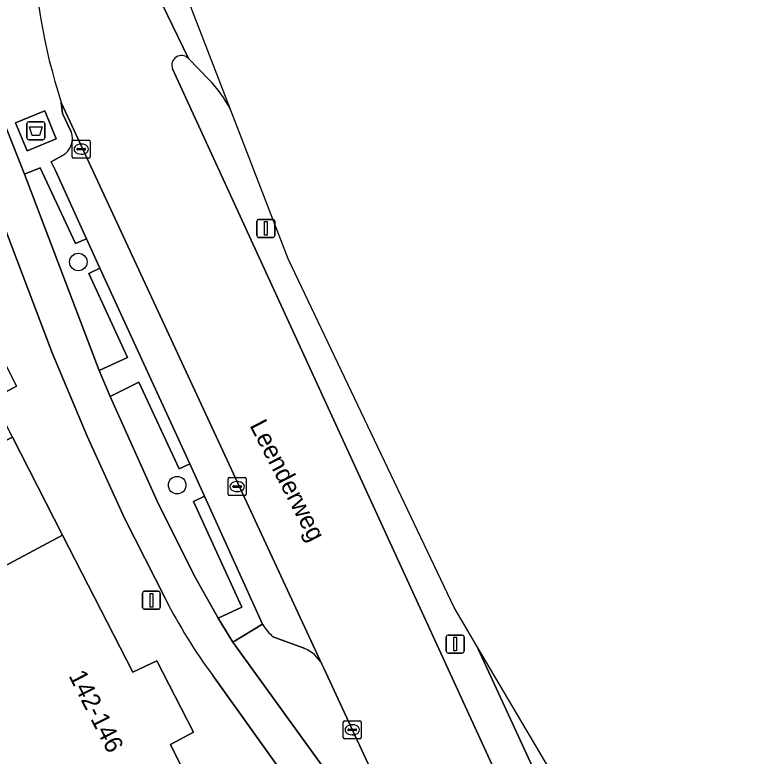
# Model space of a CAD drawing. Extents: x 161838 to 162344, y 381620 to 382160.
# Drawn here: x 162293.12 to 162333.76, y 381715.15 to 381756.3 of the extents above; entities that cross this region are included whole.
import ezdxf

# ---------------------------------------------------------------- set-up
doc = ezdxf.new("R2010")
doc.units = 0
for name, color, linetype in [('IMGEO_Afval_apart_plaats', 7, 'Continuous'), ('IMGEO_Berm_groen', 7, 'Continuous'), ('IMGEO_Boom', 7, 'Continuous'), ('IMGEO_Kolk', 7, 'Continuous'), ('IMGEO_Lichtmast', 7, 'Continuous'), ('IMGEO_Openbare_ruimte_label', 7, 'Continuous'), ('IMGEO_Pand', 7, 'Continuous'), ('IMGEO_Pand_nummerreeks', 7, 'Continuous'), ('IMGEO_Parkeervlak_open', 7, 'Continuous'), ('IMGEO_Rijbaan_lokaal_gesloten', 7, 'Continuous'), ('IMGEO_Verkeerseiland_open', 7, 'Continuous'), ('IMGEO_Voetpad_gesloten', 7, 'Continuous'), ('IMGEO_Voetpad_open', 7, 'Continuous')]:
    doc.layers.add(name, color=color, linetype=linetype)

msp = doc.modelspace()

# ---------------------------------------------------------------- linework, layer by layer
at = {"layer": 'IMGEO_Afval_apart_plaats'}
for p, q in [((162293.788, 381749.468), (162293.788, 381750.268)), ((162293.788, 381750.268), (162293.788, 381749.468)), ((162293.888, 381750.368), (162294.678, 381750.368)), ((162294.678, 381750.368), (162293.888, 381750.368)), ((162294.778, 381750.268), (162294.778, 381749.468)), ((162294.778, 381749.468), (162294.778, 381750.268)), ((162294.678, 381749.368), (162293.888, 381749.368)), ((162293.888, 381749.368), (162294.678, 381749.368))]:
    msp.add_line(p, q, dxfattribs=at)
msp.add_lwpolyline([(162293.931, 381750.082), (162294.635, 381750.082), (162294.486, 381749.612), (162294.08, 381749.612), (162293.931, 381750.082)], dxfattribs=at)
for centre, start, end in [((162293.888, 381750.268), 90, 180), ((162293.888, 381750.268), 90, 180), ((162294.678, 381750.268), 0, 90), ((162294.678, 381750.268), 360, 90), ((162293.888, 381749.468), 180, 270), ((162293.888, 381749.468), 180, 270), ((162294.678, 381749.468), 270, 0), ((162294.678, 381749.468), 270, 0)]:
    msp.add_arc(centre, 0.1, start, end, dxfattribs=at)
at = {"layer": 'IMGEO_Berm_groen'}
for points in [[(162297.084, 381743.867), (162296.479, 381743.618), (162294.53, 381747.813), (162293.643, 381747.456), (162297.795, 381736.557), (162299.371, 381737.283), (162297.229, 381741.95), (162297.836, 381742.243)], [(162303.648, 381729.58), (162302.821, 381731.377), (162302.228, 381731.099), (162300.005, 381735.91), (162298.402, 381735.121), (162301.083, 381729.14), (162303.141, 381725.051), (162304.396, 381722.807), (162305.722, 381723.43), (162303.034, 381729.292)]]:
    msp.add_lwpolyline(points, close=True, dxfattribs=at)
for points in [[(162306.86, 381722.485), (162305.205, 381721.481), (162310.281, 381714.458)], [(162309.164, 381721.136), (162307.481, 381721.765)], [(162310.249, 381720.064), (162310.161, 381720.255)], [(162319.738, 381699.582), (162310.249, 381720.064)]]:
    msp.add_lwpolyline(points, dxfattribs=at)
for centre, radius, start, end in [((162308.749, 381723.486), 2.138, 207.9295, 233.626), ((162308.478, 381719.355), 1.908, 28.1321, 68.9369)]:
    msp.add_arc(centre, radius, start, end, dxfattribs=at)
at = {"layer": 'IMGEO_Boom'}
for centre in [(162296.638, 381742.582), (162302.124, 381730.193)]:
    msp.add_circle(centre, 0.489, dxfattribs=at)
at = {"layer": 'IMGEO_Kolk'}
for p, q in [((162296.302, 381748.421), (162296.302, 381749.273)), ((162296.377, 381749.347), (162297.229, 381749.347)), ((162297.303, 381749.273), (162297.303, 381748.421)), ((162296.561, 381748.841), (162296.561, 381748.853)), ((162296.999, 381748.804), (162296.601, 381748.804)), ((162296.604, 381748.89), (162297.002, 381748.89)), ((162296.79, 381749.127), (162296.815, 381749.127)), ((162297.045, 381748.853), (162297.045, 381748.841)), ((162297.229, 381748.347), (162296.377, 381748.347)), ((162296.813, 381748.567), (162296.788, 381748.567)), ((162304.953, 381729.689), (162304.953, 381730.541)), ((162305.028, 381730.615), (162305.88, 381730.615)), ((162305.441, 381730.395), (162305.466, 381730.395)), ((162305.954, 381730.541), (162305.954, 381729.689)), ((162305.212, 381730.109), (162305.212, 381730.121)), ((162305.65, 381730.072), (162305.252, 381730.072)), ((162305.255, 381730.158), (162305.653, 381730.158)), ((162305.464, 381729.835), (162305.439, 381729.835)), ((162305.696, 381730.121), (162305.696, 381730.109)), ((162305.88, 381729.615), (162305.028, 381729.615)), ((162311.417, 381717.114), (162312.269, 381717.114)), ((162311.342, 381716.188), (162311.342, 381717.04)), ((162311.644, 381716.657), (162312.042, 381716.657)), ((162311.83, 381716.894), (162311.855, 381716.894)), ((162312.343, 381717.04), (162312.343, 381716.188)), ((162311.601, 381716.608), (162311.601, 381716.62)), ((162312.039, 381716.571), (162311.641, 381716.571)), ((162311.853, 381716.334), (162311.828, 381716.334)), ((162312.085, 381716.62), (162312.085, 381716.608)), ((162312.269, 381716.114), (162311.417, 381716.114))]:
    msp.add_line(p, q, dxfattribs=at)
for points in [[(162296.302, 381748.421), (162296.302, 381749.273)], [(162296.377, 381749.347), (162297.229, 381749.347)], [(162297.303, 381749.273), (162297.303, 381748.421)], [(162297.229, 381748.347), (162296.377, 381748.347)], [(162304.953, 381729.689), (162304.953, 381730.541)], [(162305.028, 381730.615), (162305.88, 381730.615)], [(162305.954, 381730.541), (162305.954, 381729.689)], [(162305.88, 381729.615), (162305.028, 381729.615)], [(162311.417, 381717.114), (162312.269, 381717.114)], [(162311.342, 381716.188), (162311.342, 381717.04)], [(162312.343, 381717.04), (162312.343, 381716.188)], [(162312.269, 381716.114), (162311.417, 381716.114)]]:
    msp.add_lwpolyline(points, dxfattribs=at)
for centre, radius, start, end in [((162296.379, 381749.271), 0.0765, 91.552, 178.448), ((162296.379, 381749.271), 0.0765, 91.552, 178.448), ((162297.227, 381749.271), 0.0765, 1.552, 88.448), ((162297.227, 381749.271), 0.0765, 1.552, 88.448), ((162296.601, 381748.85), 0.0403, 85.8775, 175.7526), ((162296.598, 381748.84), 0.0366, 178.938, 274.7102), ((162297.002, 381748.847), 0.043, 264.8664, 352.4533), ((162297.006, 381748.852), 0.0386, 1.7309, 96.639), ((162296.379, 381748.423), 0.0765, 181.552, 268.448), ((162296.379, 381748.423), 0.0765, 181.552, 268.448), ((162297.227, 381748.423), 0.0765, 271.552, 358.448), ((162297.227, 381748.423), 0.0765, 271.552, 358.448), ((162305.03, 381730.539), 0.0765, 91.552, 178.448), ((162305.03, 381730.539), 0.0765, 91.552, 178.448), ((162305.878, 381730.539), 0.0765, 1.552, 88.448), ((162305.878, 381730.539), 0.0765, 1.552, 88.448), ((162305.252, 381730.118), 0.0403, 85.8775, 175.7526), ((162305.249, 381730.108), 0.0366, 178.938, 274.7102), ((162305.653, 381730.115), 0.043, 264.8664, 352.4533), ((162305.657, 381730.12), 0.0386, 1.7309, 96.639), ((162305.03, 381729.691), 0.0765, 181.552, 268.448), ((162305.03, 381729.691), 0.0765, 181.552, 268.448), ((162305.878, 381729.691), 0.0765, 271.552, 358.448), ((162305.878, 381729.691), 0.0765, 271.552, 358.448), ((162311.419, 381717.038), 0.0765, 91.552, 178.448), ((162311.419, 381717.038), 0.0765, 91.552, 178.448), ((162312.267, 381717.038), 0.0765, 1.552, 88.448), ((162312.267, 381717.038), 0.0765, 1.552, 88.448), ((162311.641, 381716.617), 0.0403, 85.8775, 175.7526), ((162312.046, 381716.619), 0.0386, 1.7309, 96.639), ((162311.638, 381716.607), 0.0366, 178.938, 274.7102), ((162312.042, 381716.614), 0.043, 264.8664, 352.4533), ((162311.419, 381716.19), 0.0765, 181.552, 268.448), ((162311.419, 381716.19), 0.0765, 181.552, 268.448), ((162312.267, 381716.19), 0.0765, 271.552, 358.448), ((162312.267, 381716.19), 0.0765, 271.552, 358.448)]:
    msp.add_arc(centre, radius, start, end, dxfattribs=at)
for centre, major_axis, ratio, start_param, end_param in [((162296.789, 381748.847), (-0.387, 0.002), 0.722429, 4.712389, 7.853982), ((162296.814, 381748.847), (-0.39, 0.002), 0.717154, 1.570796, 4.712389), ((162305.44, 381730.115), (-0.387, 0.002), 0.722429, 4.712389, 7.853982), ((162305.465, 381730.115), (-0.39, 0.002), 0.717154, 1.570796, 4.712389), ((162311.829, 381716.614), (-0.387, 0.002), 0.722429, 4.712389, 7.853982), ((162311.854, 381716.614), (-0.39, 0.002), 0.717154, 1.570796, 4.712389)]:
    msp.add_ellipse(centre, major_axis=major_axis, ratio=ratio, start_param=start_param, end_param=end_param, dxfattribs=at)
at = {"layer": 'IMGEO_Lichtmast'}
for p, q in [((162306.546, 381744.047), (162306.546, 381744.847)), ((162306.546, 381744.847), (162306.546, 381744.047)), ((162306.646, 381744.947), (162307.436, 381744.947)), ((162307.436, 381744.947), (162306.646, 381744.947)), ((162307.536, 381744.847), (162307.536, 381744.047)), ((162307.536, 381744.047), (162307.536, 381744.847)), ((162307.436, 381743.947), (162306.646, 381743.947)), ((162306.646, 381743.947), (162307.436, 381743.947)), ((162300.2, 381723.403), (162300.2, 381724.203)), ((162300.2, 381724.203), (162300.2, 381723.403)), ((162300.3, 381724.303), (162301.09, 381724.303)), ((162301.09, 381724.303), (162300.3, 381724.303)), ((162301.19, 381724.203), (162301.19, 381723.403)), ((162301.19, 381723.403), (162301.19, 381724.203)), ((162301.09, 381723.303), (162300.3, 381723.303)), ((162300.3, 381723.303), (162301.09, 381723.303)), ((162317.059, 381720.976), (162317.059, 381721.776)), ((162317.059, 381721.776), (162317.059, 381720.976)), ((162317.159, 381721.876), (162317.949, 381721.876)), ((162317.949, 381721.876), (162317.159, 381721.876)), ((162318.049, 381721.776), (162318.049, 381720.976)), ((162318.049, 381720.976), (162318.049, 381721.776)), ((162317.949, 381720.876), (162317.159, 381720.876)), ((162317.159, 381720.876), (162317.949, 381720.876))]:
    msp.add_line(p, q, dxfattribs=at)
for points in [[(162306.966, 381744.822), (162307.116, 381744.822), (162307.116, 381744.072), (162306.966, 381744.072), (162306.966, 381744.822)], [(162300.62, 381724.178), (162300.77, 381724.178), (162300.77, 381723.428), (162300.62, 381723.428), (162300.62, 381724.178)], [(162317.479, 381721.751), (162317.629, 381721.751), (162317.629, 381721.001), (162317.479, 381721.001), (162317.479, 381721.751)]]:
    msp.add_lwpolyline(points, dxfattribs=at)
for centre, start, end in [((162306.646, 381744.847), 90, 180), ((162306.646, 381744.847), 90, 180), ((162307.436, 381744.847), 0, 90), ((162307.436, 381744.847), 360, 90), ((162306.646, 381744.047), 180, 270), ((162306.646, 381744.047), 180, 270), ((162307.436, 381744.047), 270, 0), ((162307.436, 381744.047), 270, 0), ((162300.3, 381724.203), 90, 180), ((162300.3, 381724.203), 90, 180), ((162301.09, 381724.203), 0, 90), ((162301.09, 381724.203), 360, 90), ((162300.3, 381723.403), 180, 270), ((162300.3, 381723.403), 180, 270), ((162301.09, 381723.403), 270, 0), ((162301.09, 381723.403), 270, 0), ((162317.159, 381721.776), 90, 180), ((162317.159, 381721.776), 90, 180), ((162317.949, 381721.776), 0, 90), ((162317.949, 381721.776), 360, 90), ((162317.159, 381720.976), 180, 270), ((162317.159, 381720.976), 180, 270), ((162317.949, 381720.976), 270, 0), ((162317.949, 381720.976), 270, 0)]:
    msp.add_arc(centre, 0.1, start, end, dxfattribs=at)
at = {"layer": 'IMGEO_Pand'}
for points in [[(162282.773, 381735.409), (162285.9, 381729.254), (162292.991, 381732.858), (162291.9, 381734.993), (162293.213, 381735.693), (162291.185, 381739.692), (162289.867, 381739.014)], [(162285.9, 381729.254), (162286.145, 381728.771), (162284.765, 381728.073), (162287.364, 381722.942), (162295.769, 381727.423), (162292.991, 381732.858)], [(162296.995, 381703.932), (162305.503, 381708.242), (162301.748, 381715.79), (162303.026, 381716.487), (162300.998, 381720.448), (162299.66, 381719.808), (162295.769, 381727.423), (162287.364, 381722.942), (162294.839, 381708.188)]]:
    msp.add_lwpolyline(points, close=True, dxfattribs=at)
at = {"layer": 'IMGEO_Parkeervlak_open'}
for points in [[(162310.161, 381720.255), (162295.695, 381751.431), (162295.755, 381750.831), (162296.234, 381749.807)], [(162295.76, 381748.502), (162295.14, 381748.145), (162295.356, 381747.694), (162297.084, 381743.867), (162297.836, 381742.243), (162302.821, 381731.377), (162303.648, 381729.58), (162306.86, 381722.485)], [(162307.481, 381721.765), (162309.164, 381721.136)]]:
    msp.add_lwpolyline(points, dxfattribs=at)
for centre, radius, start, end in [((162295.27, 381749.419), 1.039, 298.1252, 21.9509), ((162308.749, 381723.486), 2.138, 207.9295, 233.626), ((162308.478, 381719.355), 1.908, 28.1321, 68.9369)]:
    msp.add_arc(centre, radius, start, end, dxfattribs=at)
at = {"layer": 'IMGEO_Rijbaan_lokaal_gesloten'}
for points in [[(162305.075, 381751.053), (162300.951, 381761.738), (162297.043, 381771.864), (162287.214, 381785.531), (162272.258, 381792.447), (162270.956, 381793.049), (162270.414, 381791.728), (162278.312, 381787.616)], [(162302.75, 381753.874), (162295.318, 381769.244), (162292.781, 381771.328)], [(162295.318, 381769.244), (162302.75, 381753.874), (162303.888, 381752.705)], [(162326.921, 381698.993), (162325.155, 381702.899), (162324.878, 381703.181), (162301.871, 381753.308)], [(162295.695, 381751.431), (162310.161, 381720.255), (162310.249, 381720.064), (162319.738, 381699.582)], [(162333.756, 381695.892), (162318.739, 381721.3), (162322.39, 381713.347)]]:
    msp.add_lwpolyline(points, dxfattribs=at)
for centre, radius, start, end in [((162326.441, 381761.439), 32.333, 180.762, 198.0307), ((162302.362, 381753.511), 0.531, 43.0387, 202.5173), ((162299.246, 381748.115), 6.528, 26.7478, 44.6769)]:
    msp.add_arc(centre, radius, start, end, dxfattribs=at)
at = {"layer": 'IMGEO_Verkeerseiland_open'}
for points in [[(162303.888, 381752.705), (162302.75, 381753.874)], [(162301.871, 381753.308), (162324.878, 381703.181), (162325.155, 381702.899), (162325.585, 381702.924), (162326.9, 381703.755)], [(162322.39, 381713.347), (162318.739, 381721.3), (162317.493, 381723.408), (162308.281, 381742.749), (162305.075, 381751.053)]]:
    msp.add_lwpolyline(points, dxfattribs=at)
for centre, radius, start, end in [((162302.362, 381753.511), 0.531, 43.0387, 202.5173), ((162299.246, 381748.115), 6.528, 26.7478, 44.6769)]:
    msp.add_arc(centre, radius, start, end, dxfattribs=at)
at = {"layer": 'IMGEO_Voetpad_gesloten'}
for points in [[(162125.545, 381859.011), (162130.429, 381854.037), (162134.882, 381849.978), (162140.263, 381845.513), (162147.552, 381840.181), (162154.18, 381835.7), (162160.086, 381831.935), (162165.238, 381828.801), (162168.761, 381826.912), (162197.313, 381814.891), (162266.754, 381783.434), (162271.828, 381781.089), (162275.072, 381778.709), (162277.759, 381775.733), (162280.091, 381772.447), (162282.076, 381768.974), (162284.268, 381764.473), (162289.497, 381752.523), (162295.191, 381737.537), (162297.128, 381732.914), (162299.208, 381728.355), (162301.472, 381723.885)], [(162310.281, 381714.458), (162305.205, 381721.481), (162304.396, 381722.807), (162303.141, 381725.051), (162301.083, 381729.14), (162298.402, 381735.121), (162297.795, 381736.557), (162293.643, 381747.456), (162291.289, 381753.398), (162289.504, 381757.563)], [(162304.099, 381719.625), (162308.746, 381713.124)]]:
    msp.add_lwpolyline(points, dxfattribs=at)
msp.add_lwpolyline([(162294.773, 381750.974), (162293.159, 381750.315), (162293.793, 381748.761), (162295.407, 381749.42)], close=True, dxfattribs=at)
msp.add_arc((162328.661, 381737.712), 30.503, 206.955, 216.3665, dxfattribs=at)
at = {"layer": 'IMGEO_Voetpad_open'}
for points in [[(162294.11, 381761.009), (162292.955, 381759.774), (162291.89, 381758.597), (162289.504, 381757.563), (162291.289, 381753.398), (162293.643, 381747.456), (162294.53, 381747.813), (162296.479, 381743.618), (162297.084, 381743.867), (162295.356, 381747.694), (162295.14, 381748.145), (162295.76, 381748.502)], [(162301.472, 381723.885), (162299.208, 381728.355), (162297.128, 381732.914), (162295.191, 381737.537), (162289.497, 381752.523)], [(162296.234, 381749.807), (162295.755, 381750.831), (162295.695, 381751.431)], [(162291.185, 381739.692), (162293.213, 381735.693), (162291.9, 381734.993)], [(162292.991, 381732.858), (162295.769, 381727.423), (162299.66, 381719.808), (162300.998, 381720.448), (162303.026, 381716.487), (162301.748, 381715.79), (162305.503, 381708.242), (162306.867, 381708.921), (162312.016, 381698.769), (162310.45, 381697.966), (162310.892, 381697.01), (162310.379, 381695.201), (162311.283, 381694.945), (162310.212, 381691.169), (162309.308, 381691.426), (162308.795, 381689.617), (162307.931, 381689.021), (162308.972, 381687.49), (162315.636, 381691.986)], [(162308.746, 381713.124), (162304.099, 381719.625)]]:
    msp.add_lwpolyline(points, dxfattribs=at)
for points in [[(162294.773, 381750.974), (162295.407, 381749.42), (162293.793, 381748.761), (162293.159, 381750.315)], [(162297.836, 381742.243), (162297.229, 381741.95), (162299.371, 381737.283), (162297.795, 381736.557), (162298.402, 381735.121), (162300.005, 381735.91), (162302.228, 381731.099), (162302.821, 381731.377)], [(162303.648, 381729.58), (162303.034, 381729.292), (162305.722, 381723.43), (162304.396, 381722.807), (162305.205, 381721.481), (162306.86, 381722.485)]]:
    msp.add_lwpolyline(points, close=True, dxfattribs=at)
for centre, radius, start, end in [((162326.441, 381761.439), 32.333, 180.762, 198.0307), ((162295.27, 381749.419), 1.039, 298.1252, 21.9509), ((162328.661, 381737.712), 30.503, 206.955, 216.3665)]:
    msp.add_arc(centre, radius, start, end, dxfattribs=at)

# ---------------------------------------------------------------- texts
at = {"layer": 'IMGEO_Openbare_ruimte_label'}
msp.add_text('Leenderweg', height=1, rotation=297.3341, dxfattribs=at).set_placement((162306.124, 381733.51))
at = {"layer": 'IMGEO_Pand_nummerreeks'}
msp.add_text('142-146', height=1, rotation=296.9704, dxfattribs=at).set_placement((162296.083, 381719.616))

doc.saveas('drawing.dxf')
